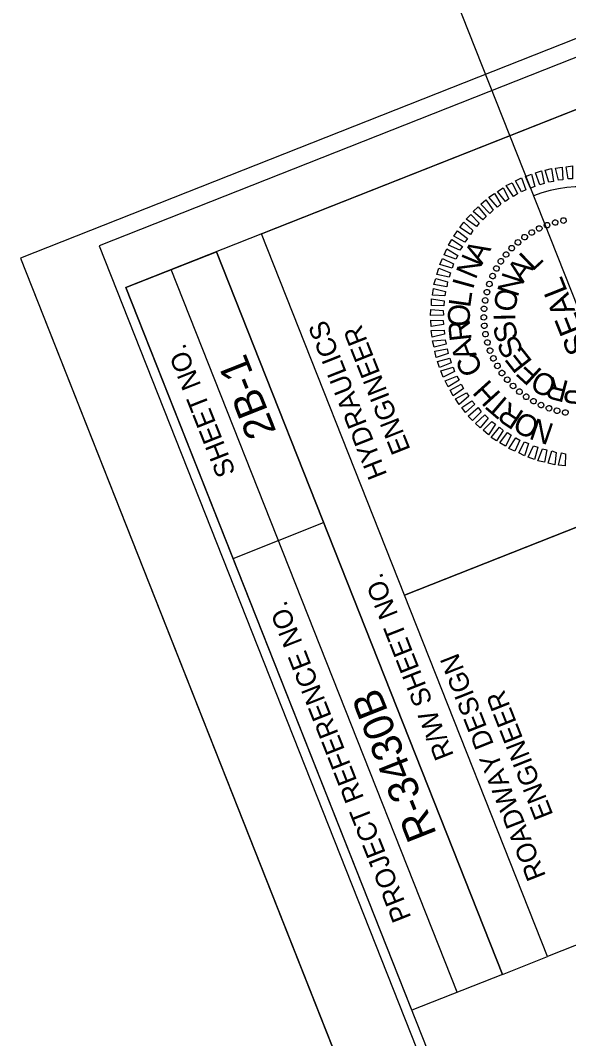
# Model space of a CAD drawing. Extents: x 1250120 to 1251758, y 748130 to 750098.
# Drawn here: x 1250120.3 to 1250261.4, y 749494.4 to 749756.6 of the extents above; entities that cross this region are included whole.
import ezdxf

# ---------------------------------------------------------------- set-up
doc = ezdxf.new("R2010")
doc.units = 0
for name, color, linetype in [('Scratch_Level_0', 7, 'Continuous'), ('Scratch_Level_1', 7, 'Continuous'), ('Sheet Cutting Line CELL', 7, 'Continuous'), ('Sheet Data Field CELL', 7, 'Continuous'), ('Sheet Plan And Profile CELL', 7, 'Continuous'), ('Sheet Plot Border Inside CELL', 7, 'Continuous'), ('Sheet Plot Border Outside CELL', 7, 'Continuous'), ('Sheet Professional Seal CELL', 7, 'Continuous')]:
    doc.layers.add(name, color=color, linetype=linetype)

msp = doc.modelspace()

# ---------------------------------------------------------------- linework, layer by layer
at = {"layer": 'Scratch_Level_0'}
msp.add_arc((1250264.67, 749680.37), 33.36, 291.5743, 111.5743, dxfattribs=at)
at = {"layer": 'Scratch_Level_1'}
msp.add_line((1250301.74, 749586.63), (1250206.96, 749826.33), dxfattribs=at)
at = {"layer": 'Sheet Cutting Line CELL'}
msp.add_line((1250120.32, 749695.34), (1250739.35, 748129.79), dxfattribs=at)
at = {"layer": 'Sheet Plan And Profile CELL'}
for p, q in [((1250244.35, 749510.98), (1250170.79, 749697.02)), ((1250232.72, 749506.39), (1250159.16, 749692.42)), ((1250219.18, 749608.62), (1250323.75, 749649.97)), ((1250175.12, 749618.08), (1250198.36, 749627.27)), ((1250244.35, 749510.98), (1250255.97, 749515.58))]:
    msp.add_line(p, q, dxfattribs=at)
for points in [[(1250147.49, 749687.81), (1250699.05, 748292.9), (1251675.49, 748678.99), (1251123.93, 750073.9)], [(1250219.18, 749608.62), (1250182.41, 749701.61), (1250287.03, 749742.98), (1250323.8, 749649.99)], [(1250221.05, 749501.77), (1250147.49, 749687.81), (1250170.79, 749697.02), (1250244.35, 749510.98)], [(1250255.97, 749515.58), (1250219.18, 749608.62), (1250323.8, 749649.99), (1250360.59, 749556.95)]]:
    msp.add_lwpolyline(points, close=True, dxfattribs=at)
at = {"layer": 'Sheet Plot Border Inside CELL'}
msp.add_lwpolyline([(1251734.26, 748537.16), (1251121.66, 750086.44), (1250140.57, 749698.51), (1250753.17, 748149.23)], close=True, dxfattribs=at)
at = {"layer": 'Sheet Plot Border Outside CELL'}
msp.add_lwpolyline([(1251757.64, 748532.43), (1251138.6, 750097.98), (1250120.32, 749695.34), (1250739.35, 748129.79)], close=True, dxfattribs=at)
at = {"layer": 'Sheet Professional Seal CELL'}
for p, q in [((1250260.09, 749705.01), (1250260.09, 749705.01)), ((1250253.83, 749703.02), (1250253.83, 749703.02)), ((1250255.86, 749703.88), (1250255.86, 749703.88)), ((1250257.96, 749704.55), (1250257.96, 749704.55)), ((1250250.04, 749700.77), (1250250.04, 749700.77)), ((1250251.94, 749701.96), (1250251.94, 749701.96)), ((1250246.74, 749697.96), (1250246.74, 749697.96)), ((1250248.31, 749699.44), (1250248.31, 749699.44)), ((1250243.95, 749694.55), (1250243.95, 749694.55)), ((1250245.3, 749696.32), (1250245.3, 749696.32)), ((1250242.79, 749692.74), (1250242.79, 749692.74)), ((1250241.8, 749690.74), (1250241.8, 749690.74)), ((1250240.37, 749686.63), (1250240.37, 749686.63)), ((1250240.98, 749688.75), (1250240.98, 749688.75)), ((1250239.87, 749684.49), (1250239.87, 749684.49)), ((1250239.65, 749682.31), (1250239.65, 749682.31)), ((1250239.55, 749680.12), (1250239.55, 749680.12)), ((1250239.67, 749677.91), (1250239.67, 749677.91)), ((1250240.03, 749675.79), (1250240.03, 749675.79)), ((1250240.49, 749673.66), (1250240.49, 749673.66)), ((1250241.16, 749671.56), (1250241.16, 749671.56)), ((1250242.02, 749669.53), (1250242.02, 749669.53)), ((1250243.09, 749667.65), (1250243.09, 749667.65)), ((1250244.27, 749665.75), (1250244.27, 749665.75)), ((1250245.6, 749664.01), (1250245.6, 749664.01)), ((1250247.08, 749662.45), (1250247.08, 749662.45)), ((1250248.72, 749661), (1250248.72, 749661)), ((1250250.49, 749659.66), (1250250.49, 749659.66)), ((1250252.3, 749658.49), (1250252.3, 749658.49)), ((1250254.3, 749657.51), (1250254.3, 749657.51)), ((1250256.29, 749656.68), (1250256.29, 749656.68)), ((1250258.42, 749656.07), (1250258.42, 749656.07)), ((1250260.55, 749655.57), (1250260.55, 749655.57))]:
    msp.add_line(p, q, dxfattribs=at)
for points in [[(1250256.28, 749714.91), (1250255.38, 749718), (1250257.04, 749718.43), (1250257.49, 749715.12)], [(1250258.8, 749715.47), (1250258.03, 749718.5), (1250259.74, 749718.8), (1250259.92, 749715.49)], [(1250261.27, 749715.75), (1250260.74, 749718.87), (1250262.4, 749719.16), (1250262.39, 749715.77)], [(1250249.31, 749712.42), (1250247.74, 749715.3), (1250249.29, 749716.01), (1250250.39, 749712.95)], [(1250251.61, 749713.39), (1250250.28, 749716.35), (1250251.86, 749716.98), (1250252.73, 749713.83)], [(1250253.96, 749714.26), (1250252.86, 749717.32), (1250254.43, 749717.83), (1250255.11, 749714.61)], [(1250245.12, 749709.96), (1250243.08, 749712.54), (1250244.55, 749713.44), (1250245.99, 749710.62)], [(1250247.19, 749711.26), (1250245.34, 749714.02), (1250246.87, 749714.79), (1250248.23, 749711.89)], [(1250241.17, 749706.89), (1250238.84, 749709.25), (1250240.08, 749710.33), (1250241.96, 749707.74)], [(1250243.11, 749708.52), (1250240.86, 749711.07), (1250242.29, 749711.96), (1250243.96, 749709.23)], [(1250239.32, 749705.19), (1250236.84, 749707.38), (1250238.09, 749708.57), (1250240.16, 749706.06)], [(1250237.69, 749703.47), (1250235.03, 749705.43), (1250236.23, 749706.6), (1250238.35, 749704.38)], [(1250234.69, 749699.49), (1250231.84, 749701), (1250232.83, 749702.41), (1250235.35, 749700.4)], [(1250236.12, 749701.45), (1250233.38, 749703.22), (1250234.42, 749704.65), (1250236.79, 749702.47)], [(1250233.43, 749697.38), (1250230.49, 749698.69), (1250231.36, 749700.16), (1250234.1, 749698.4)], [(1250232.4, 749695.09), (1250229.42, 749696.22), (1250230.1, 749697.78), (1250232.87, 749696.08)], [(1250231.43, 749692.77), (1250228.26, 749693.72), (1250228.93, 749695.28), (1250231.78, 749693.93)], [(1250230.69, 749690.43), (1250227.45, 749691.14), (1250228, 749692.76), (1250230.99, 749691.57)], [(1250230.05, 749687.98), (1250226.71, 749688.54), (1250227.21, 749690.13), (1250230.2, 749689.22)], [(1250229.51, 749685.67), (1250226.36, 749685.87), (1250226.6, 749687.58), (1250229.72, 749686.77)], [(1250229.29, 749683.1), (1250226.08, 749683.18), (1250226.16, 749684.88), (1250229.39, 749684.33)], [(1250229.23, 749680.66), (1250225.88, 749680.57), (1250225.92, 749682.1), (1250229.13, 749681.86)], [(1250229.22, 749678.24), (1250226.06, 749677.8), (1250225.96, 749679.42), (1250229.16, 749679.34)], [(1250229.5, 749675.77), (1250226.29, 749675.04), (1250226.04, 749676.77), (1250229.34, 749676.84)], [(1250229.92, 749673.19), (1250226.78, 749672.44), (1250226.41, 749674.06), (1250229.62, 749674.37)], [(1250230.43, 749670.82), (1250227.34, 749669.81), (1250227.01, 749671.45), (1250230.18, 749672.01)], [(1250231.21, 749668.44), (1250228.19, 749667.24), (1250227.63, 749668.79), (1250230.82, 749669.57)], [(1250232.05, 749666.19), (1250229.12, 749664.76), (1250228.56, 749666.31), (1250231.66, 749667.32)], [(1250233.2, 749663.95), (1250230.43, 749662.26), (1250229.62, 749663.77), (1250232.62, 749665.01)], [(1250234.36, 749661.83), (1250231.68, 749659.91), (1250230.94, 749661.39), (1250233.78, 749662.89)], [(1250235.76, 749659.8), (1250233.21, 749657.67), (1250232.26, 749659.12), (1250235.14, 749660.69)], [(1250237.24, 749657.81), (1250234.88, 749655.64), (1250233.89, 749656.91), (1250236.53, 749658.66)], [(1250238.89, 749655.82), (1250236.67, 749653.55), (1250235.56, 749654.72), (1250238.15, 749656.88)], [(1250240.67, 749654.16), (1250238.66, 749651.65), (1250237.44, 749652.83), (1250239.85, 749655.02)], [(1250242.58, 749652.61), (1250240.75, 749649.89), (1250239.44, 749651.04), (1250241.67, 749653.27)], [(1250244.55, 749651.02), (1250242.86, 749648.36), (1250241.5, 749649.22), (1250243.59, 749651.82)], [(1250246.65, 749649.8), (1250245.2, 749646.92), (1250243.73, 749647.79), (1250245.69, 749650.45)], [(1250248.82, 749648.51), (1250247.59, 749645.66), (1250246.03, 749646.33), (1250247.82, 749649.14)], [(1250251.06, 749647.62), (1250250.09, 749644.5), (1250248.56, 749645.24), (1250250.02, 749648.07)], [(1250253.47, 749646.7), (1250252.61, 749643.56), (1250251, 749644.11), (1250252.37, 749647.02)], [(1250255.79, 749646), (1250255.2, 749642.86), (1250253.5, 749643.21), (1250254.66, 749646.25)], [(1250258.2, 749645.34), (1250257.83, 749642.18), (1250256.16, 749642.6), (1250257.07, 749645.75)], [(1250260.64, 749645.01), (1250260.52, 749641.9), (1250258.81, 749642.03), (1250259.53, 749645.22)]]:
    msp.add_lwpolyline(points, close=True, dxfattribs=at)
for centre, major_axis in [((1250257.93, 749704.53), (-0.193, 0.694)), ((1250260.07, 749705.03), (-0.132, 0.708)), ((1250251.91, 749701.97), (-0.366, 0.62)), ((1250253.84, 749703), (-0.311, 0.649)), ((1250255.85, 749703.85), (-0.253, 0.674)), ((1250248.36, 749699.42), (-0.468, 0.547)), ((1250250.08, 749700.77), (-0.419, 0.586)), ((1250245.3, 749696.3), (-0.556, 0.457)), ((1250246.76, 749697.93), (-0.514, 0.504)), ((1250243.98, 749694.55), (-0.594, 0.407)), ((1250242.82, 749692.69), (-0.627, 0.354)), ((1250241.02, 749688.71), (-0.679, 0.239)), ((1250241.83, 749690.74), (-0.656, 0.298)), ((1250240.38, 749686.62), (-0.697, 0.179)), ((1250239.93, 749684.48), (-0.71, 0.118)), ((1250239.66, 749682.31), (-0.718, 0.056)), ((1250239.59, 749680.12), (-0.72, -0.007)), ((1250239.71, 749677.94), (-0.717, -0.07)), ((1250240.01, 749675.77), (-0.708, -0.132)), ((1250240.51, 749673.64), (-0.694, -0.193)), ((1250241.19, 749671.56), (-0.674, -0.253)), ((1250242.05, 749669.55), (-0.649, -0.311)), ((1250243.08, 749667.62), (-0.62, -0.366)), ((1250244.27, 749665.78), (-0.586, -0.419)), ((1250245.62, 749664.06), (-0.547, -0.468)), ((1250247.11, 749662.46), (-0.504, -0.514)), ((1250248.74, 749661), (-0.457, -0.556)), ((1250250.49, 749659.69), (-0.407, -0.594)), ((1250252.35, 749658.53), (-0.354, -0.627)), ((1250254.3, 749657.54), (-0.298, -0.656)), ((1250256.33, 749656.72), (-0.239, -0.679)), ((1250258.42, 749656.08), (-0.179, -0.697)), ((1250260.56, 749655.63), (-0.118, -0.71))]:
    msp.add_ellipse(centre, major_axis=major_axis, ratio=0.999708, dxfattribs=at)

# ---------------------------------------------------------------- texts
at = {"layer": 'Sheet Data Field CELL'}
for s, p in [('2B-1', (1250186.24, 749650.73)), ('R-3430B', (1250227.54, 749547.1))]:
    msp.add_text(s, height=7.75, rotation=111.5743, dxfattribs=at).set_placement(p)
at = {"layer": 'Sheet Plan And Profile CELL'}
for s, height, p in [('HYDRAULICS', 5, (1250214.77, 749639.62)), ('ENGINEER', 5, (1250220.77, 749646.08)), ('SHEET NO.', 5, (1250175.79, 749640.18)), ('R/W SHEET NO.', 5.0001, (1250231.94, 749567.37)), ('PROJECT REFERENCE NO.', 5.0001, (1250220.98, 749525.62)), ('ROADWAY DESIGN', 5.0001, (1250255.63, 749536.31)), ('ENGINEER', 5, (1250257.52, 749552.05))]:
    msp.add_text(s, height=height, rotation=111.5743, dxfattribs=at).set_placement(p)
at = {"layer": 'Sheet Professional Seal CELL'}
for s, height, rotation, p in [('A', 5.64, 60.1915, (1250239.1, 749693.49)), ('N', 5.64, 67.3933, (1250237.45, 749689.66)), ('A', 5.64, 53.3346, (1250249.64, 749688.73)), ('L', 5.64, 43.9752, (1250252.13, 749691.82)), ('I', 5.64, 74.5945, (1250236.79, 749687.09)), ('N', 5.64, 72.051, (1250248.27, 749685.13)), ('SEAL', 5.998, 111.5743, (1250267.11, 749671.88)), ('O', 5.64, 81.4078, (1250247.64, 749681.28)), ('L', 5.64, 81.7952, (1250236.05, 749682.45)), ('O', 5.64, 88.9955, (1250235.95, 749677.67)), ('R', 5.64, 96.1954, (1250236.48, 749674.28)), ('I', 5.64, 90.764, (1250247.73, 749679.16)), ('S', 5.64, 109.4747, (1250248.66, 749674.9)), ('A', 5.64, 110.5947, (1250237.84, 749670.3)), ('S', 5.64, 118.83, (1250250.03, 749671.57)), ('E', 5.64, 128.1854, (1250252.27, 749668.75)), ('C', 5.64, 117.7942, (1250239.57, 749666.74)), ('F', 5.64, 137.5414, (1250254.85, 749666.33)), ('O', 5.64, 156.2556, (1250258.8, 749664.34)), ('H', 5.64, 132.1938, (1250244.23, 749660.41)), ('R', 5.64, 165.614, (1250261.72, 749663.62)), ('P', 5.64, 174.9732, (1250265.29, 749663.31)), ('T', 5.64, 139.3941, (1250246.96, 749657.99)), ('R', 5.64, 146.5949, (1250250.25, 749655.64)), ('O', 5.64, 153.7961, (1250254.4, 749653.57)), ('N', 5.64, 160.9978, (1250257.95, 749652.5))]:
    msp.add_text(s, height=height, rotation=rotation, dxfattribs=at).set_placement(p)

doc.saveas('drawing.dxf')
